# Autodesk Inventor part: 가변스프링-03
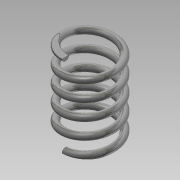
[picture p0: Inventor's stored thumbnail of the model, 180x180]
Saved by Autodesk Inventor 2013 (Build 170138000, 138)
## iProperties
Created: 2014-12
Part Number: 가변스프링-03
Material: 강철, 탄소
Document SubType Name: Modeling
Designer: hanacad19
Density: 7.87 g/cm^3
Mass: 18.8881 g
Surface Area: 32.5247 cm^2
Volume: 2.40001 cm^3
Author: hanacad19
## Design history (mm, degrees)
sketch "스케치1"
  geometry: L1 (0, 0)-(-11, 0); L2 (-11, 0)-(-11, 36.411); L3 (-11, 36.411)-(0, 36.411); L4 (0, 36.411)-(0, 0); C1 r 1.5 at (-11, 0)
  constraints: 8 end point, 2 parallel, 1 centre point, 1 horizontal, 1 perpendicular
  dimensions: "d0" = 3 diameter of C1; "d2" = 22 diameter of L2 L4; "d3" = 36.4112 distance between parallel lines of L1 L3 (derived)
feature "코일1" sketch "스케치1" pitch "d4" = 10; turns "d6" = 5; dims "d5" = 36.4112 (= d3), "d7" = 0, angle "d8" = 90 deg, angle "d9" = 90 deg, "d10" = 0, "d11" = 0
sketch "스케치2"
  geometry: L1 (0, -12.5)-(0, -9.5) reference; 1 further point
  constraints: 1 vertical alignment
extrude "돌출1" cut sketch "스케치2" distance "d12" = 10; taper "d13" = 0 deg
node "작업 평면1"
sketch "스케치3"
  geometry: L1 (0, -9.5)-(0, -12.5) reference; 1 further point
  constraints: 1 vertical alignment
extrude "돌출2" cut sketch "스케치3" distance "d14" = 10; taper "d15" = 0 deg
node "솔리드1"
node "절단 모서리 투영1"
node "절단 모서리 투영2"
